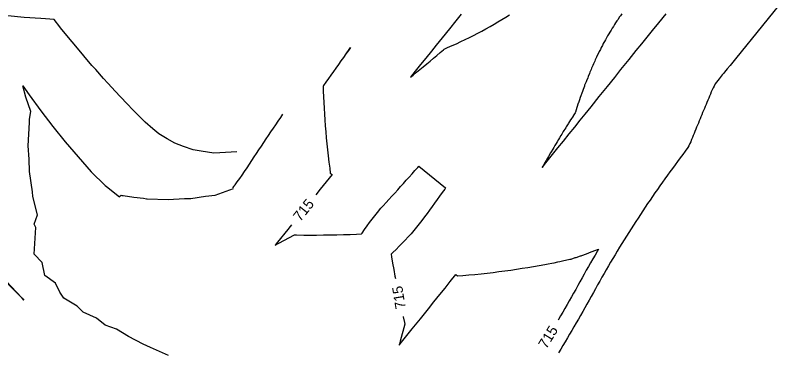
# Model space of a CAD drawing. Extents: x 1487507 to 1489130, y 497211 to 499439.
# Drawn here: x 1488655.8 to 1488835.8, y 499096.2 to 499174 of the extents above; entities that cross this region are included whole.
import ezdxf

# ---------------------------------------------------------------- set-up
doc = ezdxf.new("R2010")
doc.units = 0
for name, color, linetype in [('Prop CMT Ditch DDE', 7, 'Continuous'), ('Prop Drainage Ditch Flow Line', 7, 'Continuous'), ('Prop Drainage Structure Pipe Outlet Channel Detail CELL', 7, 'Continuous')]:
    doc.layers.add(name, color=color, linetype=linetype)

msp = doc.modelspace()

# ---------------------------------------------------------------- linework, layer by layer
at = {"layer": 'Prop CMT Ditch DDE'}
for points in [[(1488835.78, 499179.55), (1488823.22, 499163.98), (1488821.96, 499162.44), (1488821.95, 499162.43), (1488821.31, 499161.66), (1488820.68, 499160.89), (1488820.42, 499160.57), (1488820.15, 499160.24), (1488819.41, 499159.34), (1488818.78, 499158.57), (1488818.49, 499158.14), (1488818.28, 499157.65), (1488818, 499157.25), (1488817.79, 499156.75), (1488817.59, 499156.28), (1488817.38, 499155.78), (1488817.19, 499155.32), (1488816.98, 499154.82), (1488816.78, 499154.37), (1488816.57, 499153.86), (1488816.38, 499153.41), (1488816.17, 499152.91), (1488815.98, 499152.45), (1488815.77, 499151.95), (1488815.58, 499151.49), (1488815.38, 499150.99), (1488815.18, 499150.52), (1488814.98, 499150.03), (1488814.78, 499149.56), (1488814.58, 499149.07), (1488814.39, 499148.6), (1488814.18, 499148.11), (1488813.99, 499147.64), (1488813.79, 499147.14), (1488813.59, 499146.67), (1488813.39, 499146.18), (1488813.2, 499145.71), (1488813, 499145.22), (1488812.81, 499144.74), (1488812.58, 499144.28), (1488812.38, 499143.8), (1488812.16, 499143.35), (1488811.55, 499142.56), (1488810.95, 499141.76), (1488810.35, 499140.96), (1488809.75, 499140.16), (1488809.15, 499139.35), (1488808.56, 499138.55), (1488807.97, 499137.74), (1488807.38, 499136.93), (1488806.8, 499136.12), (1488806.22, 499135.3), (1488805.64, 499134.48), (1488805.06, 499133.66), (1488804.49, 499132.84), (1488803.92, 499132.01), (1488803.35, 499131.19), (1488802.79, 499130.36), (1488802.23, 499129.52), (1488801.67, 499128.69), (1488801.11, 499127.85), (1488800.56, 499127.01), (1488800.01, 499126.17), (1488799.47, 499125.32), (1488798.93, 499124.48), (1488798.39, 499123.63), (1488797.85, 499122.78), (1488797.31, 499121.92), (1488796.78, 499121.07), (1488796.25, 499120.21), (1488795.73, 499119.35), (1488795.21, 499118.48), (1488794.69, 499117.62), (1488794.17, 499116.75), (1488793.66, 499115.88), (1488793.15, 499115.01), (1488792.64, 499114.13), (1488792.14, 499113.25), (1488791.64, 499112.37), (1488791.15, 499111.48), (1488790.66, 499110.59), (1488790.17, 499109.7), (1488789.67, 499108.81), (1488789.18, 499107.93), (1488788.68, 499107.04), (1488788.18, 499106.16), (1488787.68, 499105.28), (1488787.18, 499104.4), (1488786.68, 499103.52), (1488786.17, 499102.65), (1488785.66, 499101.77), (1488785.15, 499100.9), (1488784.64, 499100.03), (1488784.12, 499099.16), (1488783.61, 499098.29), (1488783.09, 499097.42), (1488782.57, 499096.56), (1488782.05, 499095.69)], [(1488707.24, 499142.38), (1488703.31, 499142.15), (1488701.88, 499142.08), (1488698.95, 499142.52), (1488697.08, 499142.83), (1488694.83, 499143.63), (1488692.85, 499144.37), (1488691.09, 499145.39), (1488689.14, 499146.54), (1488687.75, 499147.72), (1488685.95, 499149.26), (1488684.72, 499150.51), (1488683.01, 499152.24), (1488681.84, 499153.45), (1488680.11, 499155.26), (1488679.03, 499156.43), (1488677.26, 499158.34), (1488676.27, 499159.44), (1488674.45, 499161.47), (1488673.58, 499162.47), (1488671.68, 499164.66), (1488670.98, 499165.49), (1488668.96, 499167.9), (1488668.49, 499168.48), (1488666.28, 499171.2), (1488666.09, 499171.45), (1488664.77, 499173.13), (1488662.73, 499173.25), (1488661.68, 499173.37), (1488657.79, 499173.57), (1488654, 499173.95)], [(1488759.42, 499174.33), (1488758.16, 499172.77), (1488756.7, 499170.95), (1488755.02, 499168.88), (1488753.62, 499167.14), (1488752.51, 499165.76), (1488751.17, 499164.1), (1488750, 499162.65), (1488748.74, 499161.09), (1488747.66, 499159.75), (1488748.24, 499160.21), (1488749.04, 499160.85), (1488749.83, 499161.5), (1488750.62, 499162.15), (1488751.41, 499162.8), (1488752.19, 499163.45), (1488752.97, 499164.11), (1488753.75, 499164.76), (1488754.52, 499165.43), (1488755.29, 499166.09), (1488755.47, 499166.25), (1488756.27, 499166.59), (1488757.3, 499167.04), (1488758.32, 499167.5), (1488759.33, 499167.97), (1488760.34, 499168.44), (1488761.33, 499168.93), (1488762.31, 499169.42), (1488763.28, 499169.92), (1488764.24, 499170.43), (1488765.19, 499170.95), (1488766.13, 499171.48), (1488767.06, 499172.01), (1488767.98, 499172.56), (1488768.89, 499173.11), (1488769.79, 499173.67), (1488770.68, 499174.23)], [(1488796.79, 499174.43), (1488796.49, 499173.97), (1488796.2, 499173.62), (1488795.92, 499173.15), (1488795.62, 499172.79), (1488795.35, 499172.32), (1488795.06, 499171.94), (1488794.81, 499171.48), (1488794.52, 499171.08), (1488794.28, 499170.62), (1488793.99, 499170.21), (1488793.76, 499169.75), (1488793.47, 499169.33), (1488793.25, 499168.88), (1488792.96, 499168.43), (1488792.76, 499167.99), (1488792.47, 499167.52), (1488792.28, 499167.09), (1488791.99, 499166.6), (1488791.81, 499166.18), (1488791.52, 499165.67), (1488791.36, 499165.27), (1488791.06, 499164.73), (1488790.91, 499164.34), (1488790.62, 499163.77), (1488790.48, 499163.41), (1488790.18, 499162.81), (1488790.06, 499162.46), (1488789.75, 499161.84), (1488789.64, 499161.51), (1488789.34, 499160.85), (1488789.24, 499160.55), (1488788.93, 499159.86), (1488788.84, 499159.59), (1488788.53, 499158.86), (1488788.46, 499158.61), (1488788.14, 499157.85), (1488788.08, 499157.63), (1488787.76, 499156.83), (1488787.71, 499156.65), (1488787.39, 499155.81), (1488787.35, 499155.65), (1488787.02, 499154.78), (1488786.99, 499154.66), (1488786.67, 499153.73), (1488786.65, 499153.65), (1488786.32, 499152.69), (1488786.31, 499152.64), (1488785.98, 499151.63), (1488785.98, 499151.62), (1488785.91, 499151.43), (1488785.47, 499150.74), (1488785.45, 499150.7), (1488784.93, 499149.89), (1488784.88, 499149.8), (1488784.4, 499149.04), (1488784.31, 499148.9), (1488783.86, 499148.19), (1488783.74, 499147.99), (1488783.33, 499147.33), (1488783.17, 499147.07), (1488782.81, 499146.47), (1488782.61, 499146.15), (1488782.28, 499145.61), (1488782.05, 499145.22), (1488781.76, 499144.74), (1488781.49, 499144.29), (1488781.24, 499143.88), (1488780.94, 499143.36), (1488780.73, 499143.01), (1488780.38, 499142.42), (1488780.22, 499142.14), (1488779.83, 499141.48), (1488779.71, 499141.26), (1488779.28, 499140.53), (1488779.2, 499140.39), (1488778.73, 499139.57), (1488778.7, 499139.51), (1488778.28, 499138.77), (1488779.45, 499140.23), (1488780.68, 499141.76), (1488781.94, 499143.31), (1488783.2, 499144.87), (1488784.55, 499146.56), (1488785.83, 499148.13), (1488787.1, 499149.71), (1488788.22, 499151.1), (1488789.64, 499152.86), (1488791.54, 499155.21), (1488793.43, 499157.56), (1488795.12, 499159.66), (1488796.59, 499161.47), (1488798.48, 499163.82), (1488800.15, 499165.89), (1488801.4, 499167.44), (1488802.66, 499169), (1488803.91, 499170.56), (1488805.38, 499172.37), (1488807.06, 499174.46)], [(1488691.39, 499095.09), (1488687.19, 499096.91), (1488685.45, 499097.74), (1488682.08, 499099.47), (1488679.27, 499101.23), (1488676.62, 499102.15), (1488674.61, 499103.72), (1488671.53, 499105.13), (1488670.17, 499106.54), (1488667.04, 499108.37), (1488666.08, 499109.81), (1488665.12, 499111.89), (1488662.58, 499113.69), (1488661.96, 499116.71), (1488660.17, 499118.61), (1488660.55, 499124.8), (1488660.17, 499125.62), (1488660.91, 499127.73), (1488659.85, 499132.04), (1488659.72, 499133.1), (1488659.03, 499137.79), (1488658.94, 499140.71), (1488658.77, 499143.78), (1488659.06, 499149.2), (1488659.08, 499149.98), (1488659.32, 499151.75), (1488658.22, 499155.11), (1488657.51, 499157.73), (1488658.96, 499155.64), (1488661.67, 499151.92), (1488664.47, 499148.27), (1488667.36, 499144.69), (1488670.34, 499141.19), (1488673.41, 499137.76), (1488676.68, 499134.53), (1488676.96, 499134.31), (1488679.97, 499131.97), (1488680.01, 499132.01), (1488680.33, 499132.33), (1488680.58, 499132.27), (1488680.85, 499132.21), (1488683.28, 499131.88), (1488685.54, 499131.59), (1488686.29, 499131.49), (1488686.42, 499131.48), (1488691.28, 499131.29), (1488695.1, 499131.52), (1488696.56, 499131.52), (1488700, 499132.08), (1488702.25, 499132.3), (1488706.47, 499133.86)], [(1488706.3, 499133.99), (1488706.61, 499134.41), (1488706.64, 499134.45), (1488706.77, 499134.61), (1488706.87, 499134.75), (1488707.35, 499135.38), (1488707.95, 499136.18), (1488708.53, 499137), (1488709.08, 499137.84), (1488709.63, 499138.68), (1488710.19, 499139.52), (1488710.74, 499140.35), (1488711.3, 499141.19), (1488711.85, 499142.03), (1488712.41, 499142.86), (1488712.97, 499143.7), (1488713.52, 499144.53), (1488714.08, 499145.37), (1488714.64, 499146.2), (1488715.2, 499147.03), (1488715.77, 499147.86), (1488716.33, 499148.69), (1488716.89, 499149.52), (1488717.46, 499150.35), (1488717.98, 499151.12)]]:
    msp.add_lwpolyline(points, dxfattribs=at)
msp.add_lwpolyline([(1488653.52, 499112.2), (1488653.48, 499112.24), (1488649.97, 499115.97), (1488653.36, 499112.57), (1488653.64, 499112.31), (1488657.26, 499108.48), (1488657.35, 499108.39), (1488657.74, 499107.95), (1488657.32, 499108.36)], close=True, dxfattribs=at)
at = {"layer": 'Prop Drainage Ditch Flow Line'}
for points in [[(1488733.66, 499166.58), (1488733.19, 499165.93), (1488732.61, 499165.11), (1488732.03, 499164.3), (1488731.45, 499163.48), (1488730.87, 499162.66), (1488730.29, 499161.84), (1488729.71, 499161.03), (1488729.13, 499160.21), (1488728.56, 499159.39), (1488727.98, 499158.57), (1488727.41, 499157.75), (1488727.32, 499157.62), (1488727.35, 499156.5), (1488727.41, 499155.17), (1488727.47, 499153.84), (1488727.55, 499152.49), (1488727.63, 499151.14), (1488727.72, 499149.78), (1488727.83, 499148.41), (1488727.94, 499147.03), (1488728.07, 499145.65), (1488728.2, 499144.26), (1488728.35, 499142.85), (1488728.51, 499141.44), (1488728.67, 499140.02), (1488728.85, 499138.6), (1488729, 499137.41), (1488729.39, 499137.1), (1488728.03, 499135.4), (1488726.65, 499133.7), (1488725.61, 499132.41)], [(1488732.75, 499165.31), (1488733.19, 499165.93), (1488733.66, 499166.58)], [(1488719.96, 499125.4), (1488719.69, 499125.06), (1488719.1, 499124.34), (1488716.73, 499121.39), (1488716.19, 499120.72), (1488717.02, 499121.15), (1488720.65, 499123.07), (1488720.67, 499123.07), (1488720.7, 499123.07), (1488721.12, 499123.07), (1488722.86, 499123.06), (1488723.15, 499123.06), (1488724.64, 499123.06), (1488725.81, 499123.06), (1488727.39, 499123.07), (1488728.95, 499123.1), (1488730.51, 499123.13), (1488732.05, 499123.17), (1488733.59, 499123.21), (1488735.11, 499123.27), (1488736.23, 499123.32), (1488736.38, 499123.53), (1488736.96, 499124.35), (1488737.55, 499125.16), (1488738.14, 499125.96), (1488738.75, 499126.76), (1488739.36, 499127.55), (1488739.99, 499128.33), (1488740.75, 499129.27), (1488741.28, 499129.85), (1488741.96, 499130.59), (1488742.63, 499131.33), (1488743.31, 499132.07), (1488743.98, 499132.82), (1488744.66, 499133.56), (1488745.33, 499134.3), (1488746, 499135.04), (1488746.67, 499135.78), (1488747.34, 499136.53), (1488748.01, 499137.27), (1488748.68, 499138.02), (1488749.35, 499138.76), (1488749.6, 499139.03), (1488755.81, 499134.03), (1488755.59, 499133.73), (1488755.01, 499132.92), (1488754.42, 499132.1), (1488753.84, 499131.29), (1488753.25, 499130.48), (1488752.67, 499129.67), (1488752.07, 499128.86), (1488751.48, 499128.06), (1488750.88, 499127.26), (1488750.27, 499126.46), (1488749.66, 499125.67), (1488749.04, 499124.88), (1488748.42, 499124.1), (1488748.09, 499123.7), (1488747.77, 499123.34), (1488747.08, 499122.61), (1488746.39, 499121.88), (1488745.69, 499121.16), (1488744.99, 499120.44), (1488744.28, 499119.73), (1488743.57, 499119.02), (1488743.12, 499118.58), (1488743.21, 499118.02), (1488743.47, 499116.53), (1488743.74, 499115.03), (1488744.02, 499113.52), (1488744.12, 499113)], [(1488745.93, 499104.17), (1488745.96, 499104.04), (1488746.26, 499102.71), (1488746.33, 499102.39), (1488746.33, 499102.37), (1488746.34, 499102.35), (1488745.24, 499098.4), (1488744.99, 499097.49), (1488745.53, 499098.17), (1488748.04, 499101.28), (1488749.93, 499103.61), (1488751.81, 499105.95), (1488753.06, 499107.51), (1488754.48, 499109.26), (1488755.68, 499110.75), (1488756.89, 499112.25), (1488758.19, 499113.87), (1488758.58, 499113.55), (1488759.78, 499113.65), (1488761.21, 499113.78), (1488762.63, 499113.92), (1488764.04, 499114.07), (1488765.44, 499114.22), (1488766.83, 499114.39), (1488768.21, 499114.56), (1488769.59, 499114.74), (1488770.95, 499114.93), (1488772.3, 499115.12), (1488773.63, 499115.33), (1488774.96, 499115.54), (1488776.28, 499115.76), (1488777.59, 499115.99), (1488778.89, 499116.23), (1488779.68, 499116.38), (1488780.54, 499116.55), (1488781.02, 499116.64), (1488781.94, 499116.83), (1488782.35, 499116.91), (1488783.33, 499117.12), (1488783.67, 499117.19), (1488784.7, 499117.42), (1488784.98, 499117.48), (1488785.94, 499117.81), (1488786.16, 499117.86), (1488787.16, 499118.21), (1488787.31, 499118.26), (1488787.46, 499118.31), (1488788.55, 499118.71), (1488789.64, 499119.12), (1488790.72, 499119.54), (1488791.38, 499119.8), (1488791.06, 499119.26), (1488790.55, 499118.39), (1488790.03, 499117.52), (1488789.53, 499116.64), (1488789.02, 499115.76), (1488788.52, 499114.88), (1488788.03, 499113.99), (1488787.54, 499113.1), (1488787.05, 499112.21), (1488786.56, 499111.33), (1488786.07, 499110.44), (1488785.57, 499109.56), (1488785.07, 499108.67), (1488784.57, 499107.79), (1488784.07, 499106.91), (1488783.56, 499106.03), (1488783.06, 499105.16), (1488782.55, 499104.28), (1488782.04, 499103.41), (1488781.95, 499103.25)]]:
    msp.add_lwpolyline(points, dxfattribs=at)

# ---------------------------------------------------------------- texts
at = {"layer": 'Prop Drainage Structure Pipe Outlet Channel Detail CELL'}
for rotation, p in [(51.1185, (1488722.02, 499126.04)), (99.2781, (1488746.56, 499106.09)), (58.594, (1488779.25, 499096.46))]:
    msp.add_text('715', height=2.4, rotation=rotation, dxfattribs=at).set_placement(p)

doc.saveas('drawing.dxf')
